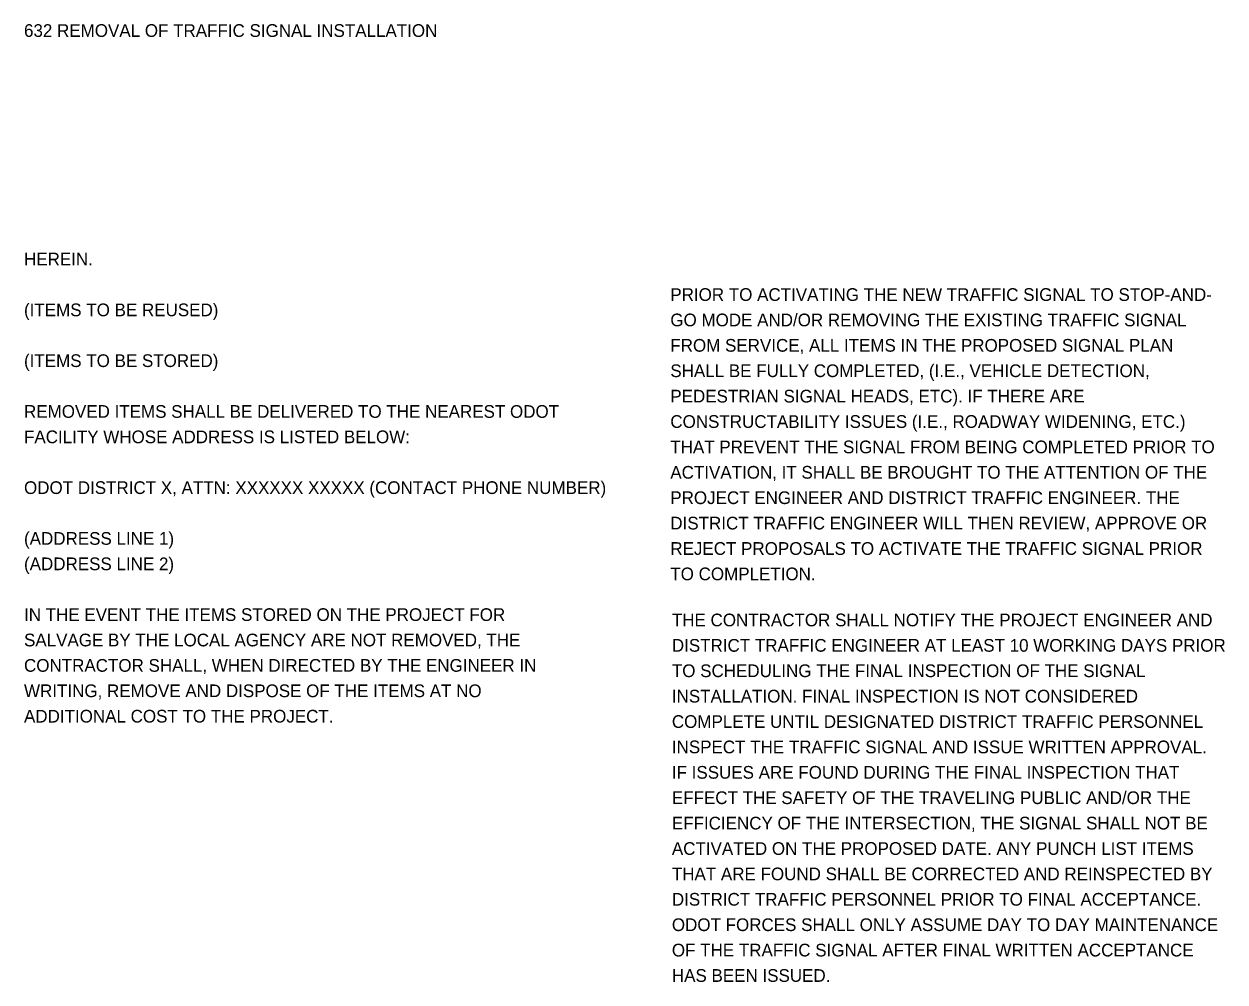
# Model space of a CAD drawing. Extents: x 0 to 54.7, y -11 to 22.
# Drawn here: x 0.79 to 14.03, y -11.02 to -0.46 of the extents above; entities that cross this region are included whole.
import ezdxf

# ---------------------------------------------------------------- set-up
doc = ezdxf.new("R2010")
doc.units = 0
doc.layers.add('SH_Text', color=7, linetype='Continuous')

msp = doc.modelspace()

# ---------------------------------------------------------------- texts
at = {"layer": 'SH_Text'}
for s, p in [('632 REMOVAL OF TRAFFIC SIGNAL INSTALLATION', (0.787, -0.602)), ('HEREIN.', (0.787, -3.122)), ('PRIOR TO ACTIVATING THE NEW TRAFFIC SIGNAL TO STOP-AND-', (7.912, -3.513)), ('(ITEMS TO BE REUSED)', (0.787, -3.682)), ('GO MODE AND/OR REMOVING THE EXISTING TRAFFIC SIGNAL', (7.912, -3.793)), ('FROM SERVICE, ALL ITEMS IN THE PROPOSED SIGNAL PLAN', (7.912, -4.073)), ('(ITEMS TO BE STORED)', (0.787, -4.242)), ('SHALL BE FULLY COMPLETED, (I.E., VEHICLE DETECTION,', (7.912, -4.353)), ('PEDESTRIAN SIGNAL HEADS, ETC). IF THERE ARE', (7.912, -4.633)), ('REMOVED ITEMS SHALL BE DELIVERED TO THE NEAREST ODOT', (0.787, -4.802)), ('CONSTRUCTABILITY ISSUES (I.E., ROADWAY WIDENING, ETC.)', (7.912, -4.913)), ('FACILITY WHOSE ADDRESS IS LISTED BELOW:', (0.787, -5.082)), ('THAT PREVENT THE SIGNAL FROM BEING COMPLETED PRIOR TO', (7.912, -5.193)), ('ACTIVATION, IT SHALL BE BROUGHT TO THE ATTENTION OF THE', (7.912, -5.473)), ('ODOT DISTRICT X, ATTN: XXXXXX XXXXX (CONTACT PHONE NUMBER)', (0.787, -5.642)), ('PROJECT ENGINEER AND DISTRICT TRAFFIC ENGINEER. THE', (7.912, -5.753)), ('DISTRICT TRAFFIC ENGINEER WILL THEN REVIEW, APPROVE OR', (7.912, -6.033)), ('(ADDRESS LINE 1)', (0.787, -6.202)), ('REJECT PROPOSALS TO ACTIVATE THE TRAFFIC SIGNAL PRIOR', (7.912, -6.313)), ('(ADDRESS LINE 2)', (0.787, -6.482)), ('TO COMPLETION.', (7.912, -6.593)), ('IN THE EVENT THE ITEMS STORED ON THE PROJECT FOR', (0.787, -7.042)), ('THE CONTRACTOR SHALL NOTIFY THE PROJECT ENGINEER AND', (7.929, -7.101)), ('SALVAGE BY THE LOCAL AGENCY ARE NOT REMOVED, THE', (0.787, -7.322)), ('DISTRICT TRAFFIC ENGINEER AT LEAST 10 WORKING DAYS PRIOR', (7.929, -7.381)), ('CONTRACTOR SHALL, WHEN DIRECTED BY THE ENGINEER IN', (0.787, -7.602)), ('TO SCHEDULING THE FINAL INSPECTION OF THE SIGNAL', (7.929, -7.661)), ('WRITING, REMOVE AND DISPOSE OF THE ITEMS AT NO', (0.787, -7.882)), ('INSTALLATION. FINAL INSPECTION IS NOT CONSIDERED', (7.929, -7.941)), ('ADDITIONAL COST TO THE PROJECT.', (0.787, -8.162)), ('COMPLETE UNTIL DESIGNATED DISTRICT TRAFFIC PERSONNEL', (7.929, -8.221)), ('INSPECT THE TRAFFIC SIGNAL AND ISSUE WRITTEN APPROVAL.', (7.929, -8.501)), ('IF ISSUES ARE FOUND DURING THE FINAL INSPECTION THAT', (7.929, -8.781)), ('EFFECT THE SAFETY OF THE TRAVELING PUBLIC AND/OR THE', (7.929, -9.061)), ('EFFICIENCY OF THE INTERSECTION, THE SIGNAL SHALL NOT BE', (7.929, -9.341)), ('ACTIVATED ON THE PROPOSED DATE. ANY PUNCH LIST ITEMS', (7.929, -9.621)), ('THAT ARE FOUND SHALL BE CORRECTED AND REINSPECTED BY', (7.929, -9.901)), ('DISTRICT TRAFFIC PERSONNEL PRIOR TO FINAL ACCEPTANCE.', (7.929, -10.181)), ('ODOT FORCES SHALL ONLY ASSUME DAY TO DAY MAINTENANCE', (7.929, -10.461)), ('OF THE TRAFFIC SIGNAL AFTER FINAL WRITTEN ACCEPTANCE', (7.929, -10.741)), ('HAS BEEN ISSUED.', (7.929, -11.021))]:
    msp.add_text(s, height=0.14, dxfattribs=at).set_placement(p)

doc.saveas('drawing.dxf')
